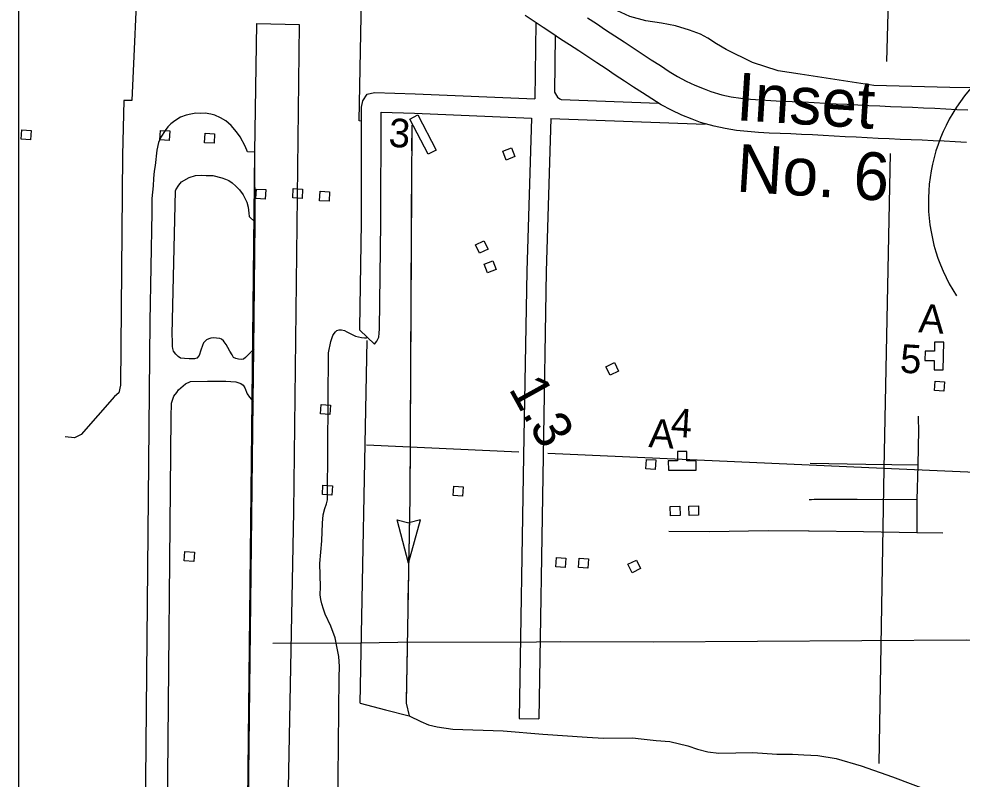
# Model space of a CAD drawing. Extents: x 1366406 to 1373462, y 376856 to 381998.
# Drawn here: x 1368990.6 to 1369108.1, y 380173.9 to 380268.5 of the extents above; entities that cross this region are included whole.
import ezdxf

# ---------------------------------------------------------------- set-up
doc = ezdxf.new("R2010")
doc.units = 0
for name, color, linetype in [('10', 7, 'Continuous'), ('33', 7, 'Continuous'), ('34', 7, 'Continuous'), ('35', 7, 'Continuous'), ('43', 7, 'Continuous'), ('46', 7, 'Continuous'), ('48', 7, 'Continuous'), ('5', 7, 'Continuous'), ('56', 7, 'Continuous'), ('57', 7, 'Continuous'), ('6', 7, 'Continuous'), ('63', 7, 'Continuous'), ('R_No Plot', 7, 'Continuous')]:
    doc.layers.add(name, color=color, linetype=linetype)

msp = doc.modelspace()

# ---------------------------------------------------------------- linework, layer by layer
at = {"layer": '10'}
for points in [[(1369074.46, 380256.01), (1369073.18, 380256.52), (1369071.88, 380257.13), (1369070.61, 380257.82), (1369069.42, 380258.55), (1369068.29, 380259.3), (1369067.17, 380260.02), (1369066.03, 380260.76), (1369064.88, 380261.51), (1369063.74, 380262.27), (1369062.6, 380263.03), (1369061.47, 380263.77), (1369060.33, 380264.52), (1369059.2, 380265.26), (1369058.07, 380266), (1369056.98, 380266.73), (1369055.89, 380267.44), (1369054.78, 380268.16), (1369053.67, 380268.92)], [(1369061.42, 380268.64), (1369062.54, 380267.91), (1369063.69, 380267.16), (1369064.84, 380266.4), (1369065.98, 380265.65), (1369067.11, 380264.89), (1369068.24, 380264.15), (1369069.37, 380263.42), (1369070.5, 380262.69), (1369071.59, 380261.97), (1369072.65, 380261.32), (1369073.7, 380260.74), (1369074.78, 380260.24), (1369075.95, 380259.78)], [(1369075.94, 380259.78), (1369076.78, 380259.45), (1369078.17, 380259.07), (1369079.33, 380258.82), (1369080.51, 380258.63), (1369081.72, 380258.5), (1369082.97, 380258.41), (1369084.26, 380258.34), (1369085.58, 380258.28), (1369086.92, 380258.22), (1369088.27, 380258.16), (1369089.64, 380258.09), (1369091.01, 380258.02), (1369092.38, 380257.94), (1369093.74, 380257.87), (1369095.09, 380257.81), (1369096.45, 380257.74), (1369097.82, 380257.67), (1369099.17, 380257.61), (1369100.53, 380257.55), (1369101.9, 380257.5), (1369103.28, 380257.44), (1369104.66, 380257.38), (1369106.04, 380257.31), (1369107.42, 380257.24), (1369108.79, 380257.18)], [(1369108.61, 380253.13), (1369107.22, 380253.2), (1369105.85, 380253.27), (1369104.48, 380253.33), (1369103.11, 380253.39), (1369101.74, 380253.45), (1369100.36, 380253.5), (1369098.98, 380253.56), (1369097.61, 380253.63), (1369096.25, 380253.7), (1369094.9, 380253.76), (1369093.53, 380253.83), (1369092.16, 380253.9), (1369090.79, 380253.98), (1369089.43, 380254.05), (1369088.08, 380254.11), (1369086.74, 380254.18), (1369085.4, 380254.23), (1369084.06, 380254.29), (1369082.71, 380254.37), (1369081.35, 380254.47), (1369079.97, 380254.61), (1369078.58, 380254.84), (1369077.2, 380255.14), (1369075.51, 380255.6), (1369074.47, 380256.01)]]:
    msp.add_lwpolyline(points, dxfattribs=at)
at = {"layer": '33'}
for points in [[(1369102.62, 380219.04), (1369102.6, 380218.68), (1369102.64, 380217.36), (1369102.55, 380212.93), (1369102.44, 380208.61), (1369102.43, 380204.51)], [(1369102.55, 380212.93), (1369096.09, 380213.01), (1369089.14, 380213.14)], [(1369102.44, 380208.61), (1369095.02, 380208.67), (1369089.65, 380208.67), (1369089.31, 380208.64), (1369089.02, 380208.62)], [(1369105.66, 380204.47), (1369102.43, 380204.51), (1369095.8, 380204.63), (1369089.02, 380204.73), (1369088.93, 380204.74), (1369083.93, 380204.77), (1369076.61, 380204.65), (1369071.57, 380204.67)]]:
    msp.add_lwpolyline(points, dxfattribs=at)
at = {"layer": '34'}
msp.add_lwpolyline([(1369030.35, 380169.91), (1369030.49, 380186.53), (1369030.53, 380187.86), (1369030.47, 380189.14), (1369030.21, 380190.35), (1369030, 380191.45), (1369029.48, 380192.88), (1369028.77, 380194.39), (1369028.57, 380195.02), (1369028.33, 380195.7), (1369028.22, 380196.23), (1369028.16, 380196.8), (1369028.18, 380197.8), (1369028.12, 380200.7), (1369028.35, 380203.53), (1369028.44, 380205.71), (1369028.5, 380206.75), (1369028.74, 380207.54), (1369028.92, 380208.15), (1369029.05, 380208.62), (1369029.07, 380209), (1369029.2, 380226.95), (1369029.48, 380228.35), (1369029.71, 380229.1), (1369029.88, 380229.32), (1369030.05, 380229.56), (1369030.22, 380229.7), (1369030.52, 380229.81), (1369030.8, 380229.81), (1369031.16, 380229.7), (1369031.45, 380229.56), (1369032.55, 380229.01), (1369033.3, 380228.82), (1369033.67, 380228.79), (1369033.85, 380228.79), (1369034.01, 380228.88)], dxfattribs=at)
at = {"layer": '35'}
for points in [[(1369120.37, 380261.48), (1369117.29, 380260.83), (1369115, 380260.53), (1369111.83, 380259.89), (1369106.55, 380259.98), (1369097.06, 380260.2), (1369087.91, 380261.63), (1369085.17, 380262.04), (1369081.99, 380263.08), (1369078.68, 380264.7), (1369077.51, 380265.4), (1369076.42, 380266.1), (1369075.48, 380266.6), (1369074.11, 380267.1), (1369072.37, 380267.62), (1369070.66, 380267.97), (1369068.68, 380268.28), (1369066.69, 380268.81), (1369065.61, 380269.32), (1369064.11, 380269.97), (1369063.92, 380270.04)], [(1369038.84, 380183.33), (1369039.24, 380181.75), (1369040.69, 380181.03), (1369041.65, 380180.62), (1369042.7, 380180.36), (1369044.66, 380180.09), (1369050.92, 380179.85), (1369055.86, 380179.44), (1369061.39, 380179.1), (1369063.42, 380178.96), (1369067.02, 380179.01), (1369068.09, 380178.89), (1369069.96, 380178.65), (1369071.66, 380178.55), (1369073.94, 380178.01), (1369075.13, 380177.58), (1369076.4, 380177.24), (1369077.79, 380177.07), (1369082, 380177.16), (1369084.99, 380176.95), (1369086.96, 380176.98), (1369088.38, 380176.87), (1369090.11, 380176.79), (1369092.39, 380176.42), (1369095.52, 380175.51), (1369099.41, 380174.15), (1369104.12, 380172.35)]]:
    msp.add_lwpolyline(points, dxfattribs=at)
at = {"layer": '43'}
for p, q in [((1369039.15, 380200.76), (1369037.74, 380206.14)), ((1369037.74, 380206.14), (1369039.17, 380205.75)), ((1369039.15, 380200.76), (1369040.62, 380206.12)), ((1369040.62, 380206.12), (1369039.19, 380205.75))]:
    msp.add_line(p, q, dxfattribs=at)
for points in [[(1369039.54, 380255.29), (1369039.3, 380208.98), (1369038.84, 380183.33)], [(1369039.54, 380255.29), (1369039.52, 380252.08)], [(1369039.51, 380249.94), (1369039.48, 380243.53)], [(1369039.46, 380241.39), (1369039.43, 380234.97)], [(1369039.42, 380232.83), (1369039.39, 380226.42)], [(1369039.38, 380224.28), (1369039.34, 380217.87)], [(1369039.33, 380215.73), (1369039.3, 380209.31)], [(1369039.27, 380207.17), (1369039.21, 380203.97)], [(1369039.21, 380203.97), (1369039.15, 380200.76)], [(1369039.11, 380198.62), (1369039, 380192.21)], [(1369171.32, 380169.64), (1369164.27, 380174.04), (1369151.99, 380181.8), (1369148.27, 380183.95), (1369146.39, 380185.29), (1369145.44, 380185.87), (1369144.38, 380186.48), (1369138.36, 380190.4), (1369137.63, 380190.73), (1369137.03, 380190.87), (1369136.27, 380190.94), (1369117.77, 380191.02), (1369114.37, 380191.09), (1369108.58, 380191.16), (1369069.61, 380190.92), (1369058.09, 380190.94), (1369055.07, 380190.89), (1369037.81, 380190.85), (1369033.17, 380190.78), (1369022.27, 380190.76)], [(1369038.96, 380190.07), (1369038.85, 380183.66)]]:
    msp.add_lwpolyline(points, dxfattribs=at)
at = {"layer": '46'}
for points in [[(1369055, 380268.02), (1369054.86, 380258.57)], [(1369057.41, 380266.44), (1369057.3, 380259.39), (1369057.31, 380259.37), (1369057.68, 380258.75), (1369057.98, 380258.55), (1369058.08, 380258.49), (1369058.17, 380258.47), (1369070.27, 380258.03)], [(1369034.91, 380228.01), (1369033.08, 380229.74), (1369033.1, 380230.04), (1369033.28, 380243.12), (1369033.31, 380257.52), (1369033.45, 380258.31), (1369034.01, 380259.12), (1369034.9, 380259.36), (1369039.96, 380259.19), (1369054.86, 380258.57)], [(1369034.91, 380228.01), (1369035.21, 380228.4), (1369035.45, 380228.88), (1369035.48, 380229.36), (1369035.53, 380229.92), (1369035.71, 380243.1), (1369035.74, 380256.9), (1369039.87, 380256.76), (1369054.45, 380256.16)], [(1369054.45, 380256.16), (1369053.87, 380237.09), (1369053.46, 380214.1), (1369052.92, 380181.42), (1369055.35, 380181.38)], [(1369056.88, 380256.09), (1369056.3, 380237.04), (1369055.89, 380214.06), (1369055.35, 380181.38)], [(1369056.88, 380256.09), (1369076.06, 380255.39)]]:
    msp.add_lwpolyline(points, dxfattribs=at)
at = {"layer": '5'}
for points in [[(1369099.62, 380298.03), (1369098.66, 380263.21)], [(1369099.12, 380251.75), (1369098.32, 380212.54)], [(1369052.86, 380214.58), (1369033.91, 380215.43)], [(1369098.32, 380212.54), (1369056.5, 380214.41)], [(1369098.32, 380212.54), (1369097.72, 380175.79)], [(1369181.98, 380208.88), (1369098.32, 380212.54)]]:
    msp.add_lwpolyline(points, dxfattribs=at)
at = {"layer": '56'}
for points in [[(1369039.32, 380256.03), (1369040.32, 380256.55), (1369042.58, 380252.17), (1369041.58, 380251.66)], [(1368990.91, 380253.52), (1368990.98, 380254.69), (1368992.16, 380254.62), (1368992.08, 380253.45)], [(1369008.18, 380253.46), (1369008.25, 380254.63), (1369009.42, 380254.55), (1369009.35, 380253.38)], [(1369013.76, 380253.09), (1369013.83, 380254.26), (1369015, 380254.18), (1369014.93, 380253.02)], [(1369051.31, 380250.93), (1369050.88, 380252.02), (1369051.97, 380252.45), (1369052.4, 380251.36)], [(1369020.13, 380246.16), (1369020.2, 380247.32), (1369021.37, 380247.25), (1369021.3, 380246.08)], [(1369024.72, 380246.21), (1369024.79, 380247.38), (1369025.96, 380247.3), (1369025.89, 380246.14)], [(1369028.08, 380245.87), (1369028.15, 380247.04), (1369029.32, 380246.96), (1369029.25, 380245.8)], [(1369047.48, 380240.39), (1369048.54, 380240.89), (1369049.04, 380239.82), (1369047.98, 380239.33)], [(1369048.97, 380236.88), (1369048.56, 380237.98), (1369049.65, 380238.39), (1369050.07, 380237.3)], [(1369105.73, 380224.81), (1369105.79, 380228.25), (1369104.64, 380228.27), (1369104.62, 380227.12), (1369103.47, 380227.14), (1369103.45, 380225.99), (1369104.6, 380225.97), (1369104.58, 380224.83)], [(1369064.24, 380224.14), (1369063.72, 380225.19), (1369064.77, 380225.71), (1369065.29, 380224.66)], [(1369104.64, 380222.22), (1369104.72, 380223.39), (1369105.89, 380223.31), (1369105.81, 380222.14)], [(1369028.18, 380219.33), (1369028.25, 380220.5), (1369029.42, 380220.43), (1369029.35, 380219.26)], [(1369068.69, 380212.49), (1369068.76, 380213.66), (1369069.94, 380213.59), (1369069.86, 380212.42)], [(1369071.5, 380212.33), (1369074.94, 380212.34), (1369074.94, 380213.49), (1369073.79, 380213.48), (1369073.79, 380214.63), (1369072.64, 380214.63), (1369072.64, 380213.48), (1369071.49, 380213.48)], [(1369028.42, 380209.3), (1369028.49, 380210.47), (1369029.66, 380210.39), (1369029.59, 380209.22)], [(1369044.71, 380209.15), (1369044.78, 380210.32), (1369045.95, 380210.25), (1369045.88, 380209.08)], [(1369071.77, 380206.64), (1369071.74, 380207.81), (1369072.92, 380207.84), (1369072.95, 380206.67)], [(1369074.09, 380206.67), (1369074.06, 380207.84), (1369075.23, 380207.88), (1369075.26, 380206.71)], [(1369011.23, 380201.03), (1369011.31, 380202.2), (1369012.48, 380202.12), (1369012.41, 380200.96)], [(1369057.49, 380200.27), (1369057.56, 380201.44), (1369058.73, 380201.36), (1369058.66, 380200.2)], [(1369060.32, 380200.21), (1369060.39, 380201.38), (1369061.57, 380201.3), (1369061.49, 380200.14)], [(1369066.99, 380199.55), (1369066.47, 380200.6), (1369067.52, 380201.12), (1369068.04, 380200.07)]]:
    msp.add_lwpolyline(points, close=True, dxfattribs=at)
at = {"layer": '57'}
for p, q in [((1369018.53, 380114.33), (1369020, 380251.91)), ((1369020.04, 380243.2), (1369020, 380251.91)), ((1369020.04, 380243.2), (1369020, 380251.91)), ((1369019.89, 380227.44), (1369020.04, 380243.2)), ((1369019.81, 380220.86), (1369019.89, 380227.44)), ((1369019.81, 380220.86), (1369019.89, 380227.44))]:
    msp.add_line(p, q, dxfattribs=at)
for points in [[(1369020, 380251.91), (1369020.25, 380267.92), (1369025.52, 380267.8), (1369024.83, 380207.13), (1369024.08, 380168.43), (1369023.28, 380102.03), (1369023.14, 380071.77), (1369023.4, 380070.55), (1369023.58, 380069.68), (1369023.78, 380069.09), (1369024.1, 380068.4), (1369024.43, 380067.7), (1369024.83, 380066.97), (1369025.3, 380066.17), (1369025.7, 380065.78), (1369025.95, 380065.23), (1369026.36, 380064.71), (1369028.75, 380062.23), (1369043.3, 380048.4), (1369064.55, 380028.1)], [(1369020, 380251.91), (1369019.11, 380251.95), (1369018.82, 380252.64), (1369018.19, 380253.82), (1369017.73, 380254.46), (1369017.07, 380255.25), (1369016.4, 380255.81), (1369015.75, 380256.2), (1369015.03, 380256.51), (1369014.51, 380256.64), (1369013.82, 380256.76), (1369013.28, 380256.74), (1369012.68, 380256.75), (1369012.02, 380256.64), (1369011.45, 380256.53), (1369010.76, 380256.26), (1369010.29, 380255.96), (1369009.9, 380255.68), (1369009.57, 380255.42), (1369009.19, 380255.08), (1369008.83, 380254.61), (1369008.3, 380253.78), (1369008.02, 380253.12), (1369007.8, 380252.16), (1369007.6, 380250.25), (1369007.47, 380249.53), (1369007.41, 380248.62), (1369007.33, 380247.72), (1369007.18, 380246.13), (1369007.17, 380244.45), (1369006.94, 380230.83), (1369006.36, 380169.39)], [(1369019.89, 380227.44), (1369019.59, 380227.11), (1369019.27, 380226.75), (1369018.85, 380226.33), (1369018.59, 380226.14), (1369018.33, 380226.12), (1369017.96, 380226.14), (1369017.66, 380226.22), (1369017.36, 380226.34), (1369017.18, 380226.69), (1369016.91, 380227.12), (1369016.65, 380227.61), (1369016.43, 380227.96), (1369016.21, 380228.29), (1369016.1, 380228.43), (1369015.84, 380228.64), (1369015.63, 380228.72), (1369015.24, 380228.76), (1369014.88, 380228.78), (1369014.54, 380228.76), (1369014.28, 380228.69), (1369014.01, 380228.54), (1369013.63, 380228.18), (1369013.48, 380227.83), (1369013.27, 380227.25), (1369013.06, 380226.58), (1369012.78, 380226.27), (1369012.51, 380226.17), (1369012.02, 380226.18), (1369011.84, 380226.17), (1369011.27, 380226.21), (1369010.76, 380226.26), (1369010.46, 380226.46), (1369010.16, 380226.75), (1369009.89, 380227.14), (1369009.8, 380227.45), (1369009.77, 380227.72), (1369009.75, 380228.35), (1369009.7, 380229.26), (1369010.11, 380247.11), (1369010.16, 380247.22), (1369010.55, 380247.79), (1369010.89, 380248.22), (1369011.85, 380248.74), (1369012.61, 380248.99), (1369013.42, 380249.05), (1369013.95, 380249.02), (1369014.79, 380248.99), (1369015.89, 380248.73), (1369016.36, 380248.57), (1369016.79, 380248.37), (1369017.2, 380248.11), (1369017.65, 380247.67), (1369018.09, 380247.21), (1369018.54, 380246.61), (1369019, 380245.7), (1369019.18, 380245.07), (1369019.27, 380244.32), (1369019.32, 380243.92), (1369020.04, 380243.2)], [(1369009.12, 380169.8), (1369009.58, 380218.94), (1369009.64, 380220.67), (1369009.93, 380221.52), (1369010.28, 380221.99), (1369010.52, 380222.32), (1369011.1, 380222.84), (1369011.37, 380223.08), (1369012, 380223.34), (1369014.11, 380223.42), (1369016.41, 380223.39), (1369017.64, 380223.3), (1369018.25, 380223.1), (1369018.55, 380222.89), (1369018.78, 380222.56), (1369019.04, 380221.83), (1369019.35, 380221.4), (1369019.81, 380220.86)], [(1369019.26, 380170.38), (1369019.23, 380170.88), (1369019.81, 380220.86)]]:
    msp.add_lwpolyline(points, dxfattribs=at)
at = {"layer": '6'}
for points in [[(1369033.3, 380255.77), (1369033, 380255.8), (1369033.36, 380275.42), (1369005.47, 380275.8), (1369004.68, 380258.35), (1369003.7, 380258.34), (1369003.52, 380251.52), (1369003.27, 380222.91), (1369003.06, 380221.93), (1369002.53, 380221.49), (1368998.4, 380216.78), (1368997.57, 380216.33), (1368996.39, 380216.47)], [(1369033.14, 380183.33), (1369034, 380228.46)], [(1369033.14, 380183.33), (1369036.27, 380182.47), (1369039.24, 380181.75)]]:
    msp.add_lwpolyline(points, dxfattribs=at)
at = {"layer": '63'}
msp.add_arc((1369125.36, 380245.77), 21.49, 66.5152, 213.1778, dxfattribs=at)
at = {"layer": 'R_No Plot'}
msp.add_line((1368990.63, 379480.59), (1368990.63, 380368.17), dxfattribs=at)

# ---------------------------------------------------------------- texts
at = {"layer": '48'}
msp.add_text('1.3', height=4.752, rotation=298.9245, dxfattribs=at).set_placement((1369051.55, 380222.46))
at = {"layer": '56'}
for s, p in [('3', (1369036.6, 380252.6)), ('A', (1369102.58, 380229.5)), ('5', (1369100.26, 380224.48)), ('4', (1369071.72, 380216.51)), ('A', (1369068.97, 380215.2))]:
    msp.add_text(s, height=3.56, rotation=356.4139, dxfattribs=at).set_placement(p)
at = {"layer": '63'}
for s, p in [('Inset', (1369079.85, 380255.9)), ('No. 6', (1369079.86, 380247.02))]:
    msp.add_text(s, height=5.94, rotation=356.4139, dxfattribs=at).set_placement(p)

doc.saveas('drawing.dxf')
